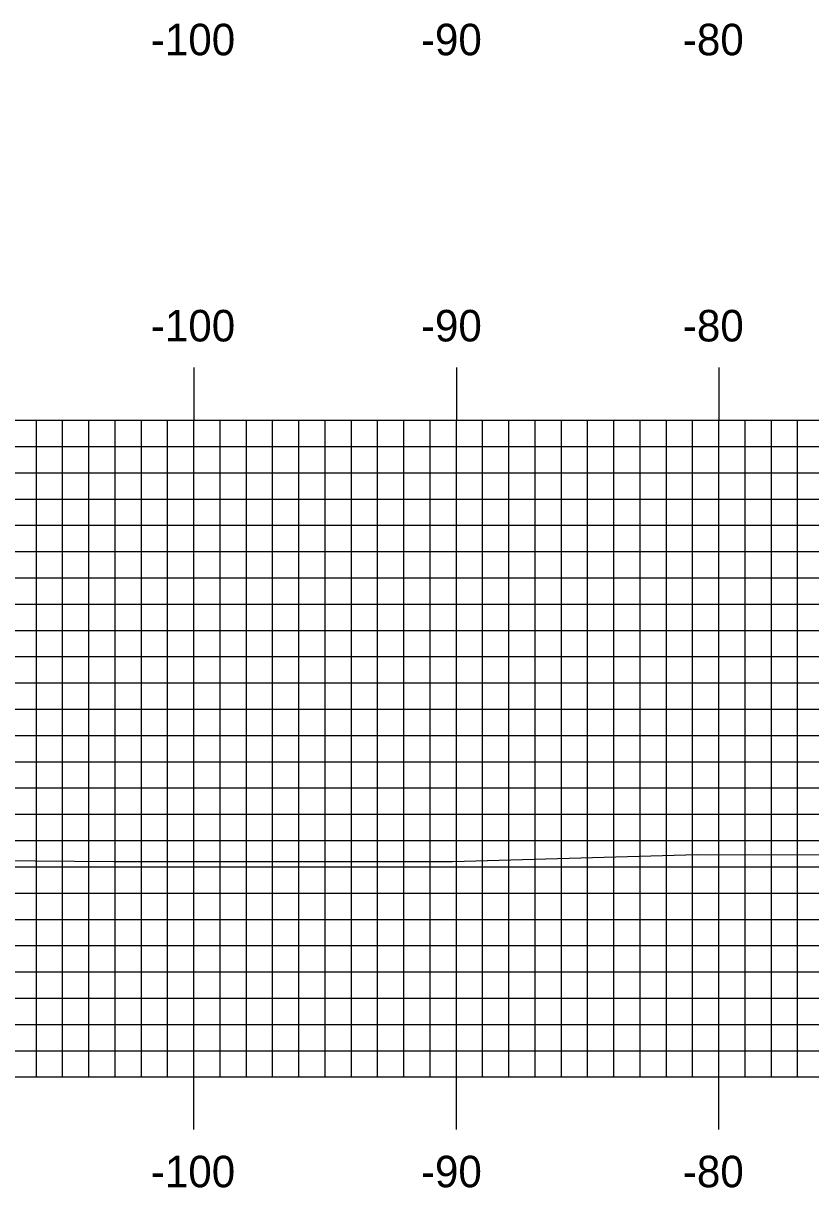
# Model space of a CAD drawing. Extents: x 852087 to 852430, y 366898 to 367118.
# Drawn here: x 852146.03 to 852176.03, y 366960.85 to 367005.18 of the extents above; entities that cross this region are included whole.
import ezdxf

# ---------------------------------------------------------------- set-up
doc = ezdxf.new("R2010")
doc.units = 0
for name, color, linetype in [('H_V ANNOTATION', 7, 'Continuous'), ('MAJOR', 7, 'Continuous'), ('MINOR', 7, 'Continuous'), ('S_Roadway_Centerline', 7, 'Continuous')]:
    doc.layers.add(name, color=color, linetype=linetype)

msp = doc.modelspace()

# ---------------------------------------------------------------- linework, layer by layer
at = {"layer": 'MAJOR'}
for p, q in [((852152.531, 366992.071), (852152.531, 366990.067)), ((852162.531, 366992.071), (852162.531, 366990.067)), ((852172.531, 366992.071), (852172.531, 366990.067)), ((852112.531, 366990.067), (852392.531, 366990.067)), ((852112.531, 366990.067), (852392.531, 366990.067)), ((852152.531, 366965.067), (852152.531, 366990.067)), ((852162.531, 366965.067), (852162.531, 366990.067)), ((852172.531, 366965.067), (852172.531, 366990.067)), ((852112.531, 366985.067), (852392.531, 366985.067)), ((852112.531, 366980.067), (852392.531, 366980.067)), ((852112.531, 366975.067), (852392.531, 366975.067)), ((852112.531, 366970.067), (852392.531, 366970.067)), ((852112.531, 366965.067), (852392.531, 366965.067)), ((852112.531, 366965.067), (852392.531, 366965.067)), ((852152.531, 366963.063), (852152.531, 366965.067)), ((852162.531, 366963.063), (852162.531, 366965.067)), ((852172.531, 366963.063), (852172.531, 366965.067))]:
    msp.add_line(p, q, dxfattribs=at)
at = {"layer": 'MINOR'}
for p, q in [((852146.531, 366965.067), (852146.531, 366990.067)), ((852147.531, 366965.067), (852147.531, 366990.067)), ((852148.531, 366965.067), (852148.531, 366990.067)), ((852149.531, 366965.067), (852149.531, 366990.067)), ((852150.531, 366965.067), (852150.531, 366990.067)), ((852151.531, 366965.067), (852151.531, 366990.067)), ((852153.531, 366965.067), (852153.531, 366990.067)), ((852154.531, 366965.067), (852154.531, 366990.067)), ((852155.531, 366965.067), (852155.531, 366990.067)), ((852156.531, 366965.067), (852156.531, 366990.067)), ((852157.531, 366965.067), (852157.531, 366990.067)), ((852158.531, 366965.067), (852158.531, 366990.067)), ((852159.531, 366965.067), (852159.531, 366990.067)), ((852160.531, 366965.067), (852160.531, 366990.067)), ((852161.531, 366965.067), (852161.531, 366990.067)), ((852163.531, 366965.067), (852163.531, 366990.067)), ((852164.531, 366965.067), (852164.531, 366990.067)), ((852165.531, 366965.067), (852165.531, 366990.067)), ((852166.531, 366965.067), (852166.531, 366990.067)), ((852167.531, 366965.067), (852167.531, 366990.067)), ((852168.531, 366965.067), (852168.531, 366990.067)), ((852169.531, 366965.067), (852169.531, 366990.067)), ((852170.531, 366965.067), (852170.531, 366990.067)), ((852171.531, 366965.067), (852171.531, 366990.067)), ((852173.531, 366965.067), (852173.531, 366990.067)), ((852174.531, 366965.067), (852174.531, 366990.067)), ((852175.531, 366965.067), (852175.531, 366990.067)), ((852112.531, 366989.067), (852392.531, 366989.067)), ((852112.531, 366988.067), (852392.531, 366988.067)), ((852112.531, 366987.067), (852392.531, 366987.067)), ((852112.531, 366986.067), (852392.531, 366986.067)), ((852112.531, 366984.067), (852392.531, 366984.067)), ((852112.531, 366983.067), (852392.531, 366983.067)), ((852112.531, 366982.067), (852392.531, 366982.067)), ((852112.531, 366981.067), (852392.531, 366981.067)), ((852112.531, 366979.067), (852392.531, 366979.067)), ((852112.531, 366978.067), (852392.531, 366978.067)), ((852112.531, 366977.067), (852392.531, 366977.067)), ((852112.531, 366976.067), (852392.531, 366976.067)), ((852112.531, 366974.067), (852392.531, 366974.067)), ((852112.531, 366973.067), (852392.531, 366973.067)), ((852112.531, 366972.067), (852392.531, 366972.067)), ((852112.531, 366971.067), (852392.531, 366971.067)), ((852112.531, 366969.067), (852392.531, 366969.067)), ((852112.531, 366968.067), (852392.531, 366968.067)), ((852112.531, 366967.067), (852392.531, 366967.067)), ((852112.531, 366966.067), (852392.531, 366966.067))]:
    msp.add_line(p, q, dxfattribs=at)
at = {"layer": 'S_Roadway_Centerline'}
msp.add_lwpolyline([(852112.531, 366973.863), (852124.679, 366973.487), (852133.774, 366973.357), (852140.47, 366973.346), (852149.481, 366973.274), (852162.384, 366973.27), (852171.723, 366973.531), (852178.063, 366973.523), (852179.534, 366973.462), (852186.982, 366974.202), (852188.594, 366974.376), (852188.839, 366974.381), (852191.071, 366974.666), (852199.747, 366975.695), (852204.722, 366976.201), (852217.909, 366978.1)], dxfattribs=at)

# ---------------------------------------------------------------- texts
at = {"layer": 'H_V ANNOTATION'}
for s, p in [('-100', (852150.893, 367003.961)), ('-90', (852161.182, 367003.961)), ('-80', (852171.161, 367003.961)), ('-100', (852150.893, 366993.067)), ('-90', (852161.182, 366993.067)), ('-80', (852171.161, 366993.067)), ('-100', (852150.893, 366960.867)), ('-90', (852161.182, 366960.867)), ('-80', (852171.161, 366960.867))]:
    msp.add_text(s, height=1.2, dxfattribs=at).set_placement(p)

doc.saveas('drawing.dxf')
